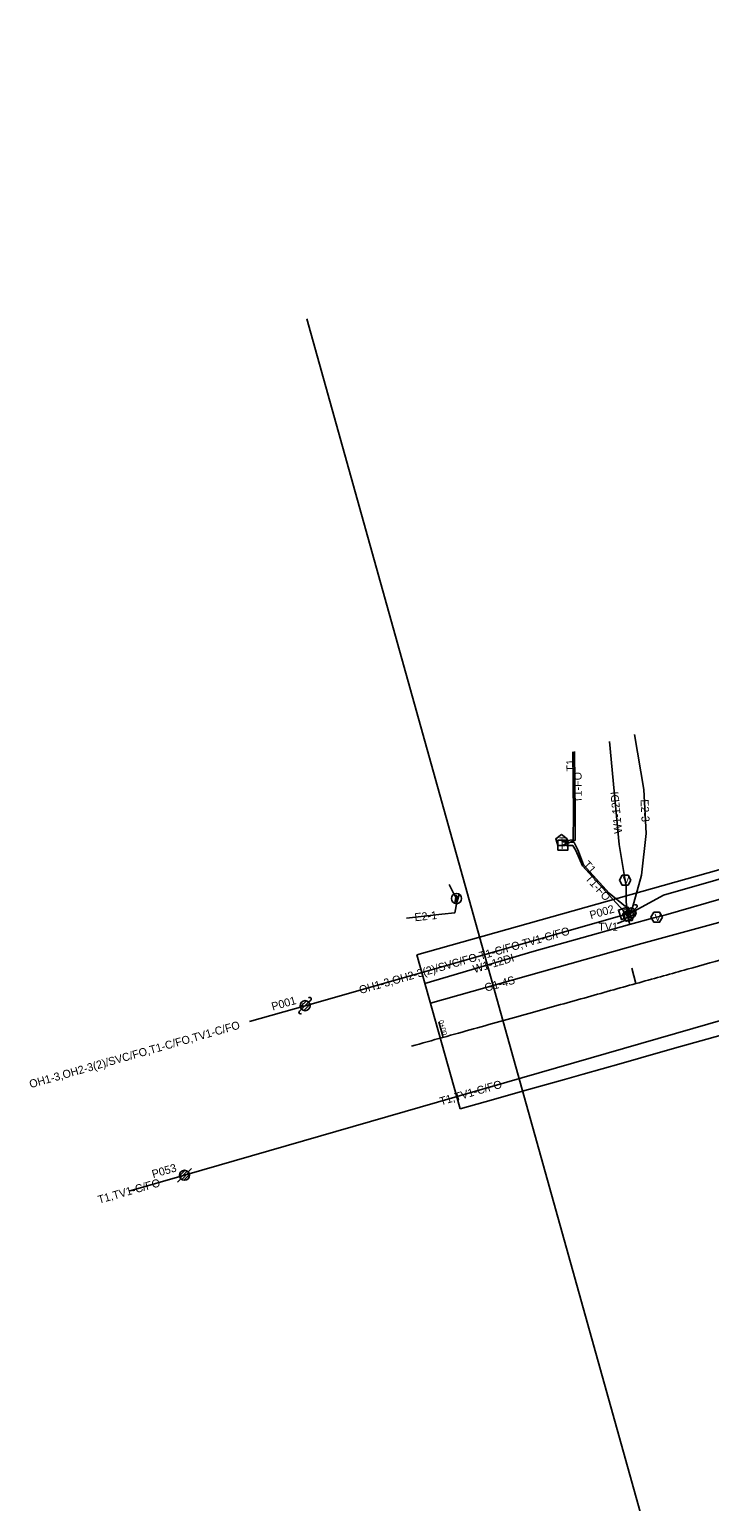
# Model space of a CAD drawing. Extents: x 1991878 to 2008544, y 770238 to 1141211.
# Drawn here: x 2002746 to 2003086, y 1138328 to 1139064 of the extents above; entities that cross this region are included whole.
import ezdxf

# ---------------------------------------------------------------- set-up
doc = ezdxf.new("R2010")
doc.units = 0
for name, color, linetype in [('Default', 7, 'Continuous'), ('RD_EX_SU_Elec', 7, 'Continuous'), ('RD_EX_SU_Gas', 7, 'Continuous'), ('RD_EX_SU_H2O', 7, 'Continuous'), ('RD_EX_SU_Ovhd', 7, 'Continuous'), ('RD_EX_SU_Pole', 7, 'Continuous'), ('RD_EX_SU_SwpLmt', 7, 'Continuous'), ('RD_EX_SU_Telecom', 7, 'Continuous'), ('RD_EX_SU_TX_Elec', 7, 'Continuous'), ('RD_EX_SU_TX_Gas', 7, 'Continuous'), ('RD_EX_SU_TX_H2O', 7, 'Continuous'), ('RD_EX_SU_TX_Ovhd', 7, 'Continuous'), ('RD_EX_SU_TX_Pole', 7, 'Continuous'), ('RD_EX_SU_TX_Telecom', 7, 'Continuous'), ('RD_HC_Cl', 7, 'Continuous')]:
    doc.layers.add(name, color=color, linetype=linetype)

msp = doc.modelspace()

# ---------------------------------------------------------------- linework, layer by layer
at = {"layer": 'RD_EX_SU_Elec'}
for points in [[(2003048.81, 1138711.86), (2003053.41, 1138684.46), (2003054.61, 1138662.45), (2003052.25, 1138641.53), (2003047.56, 1138624.68), (2003047.01, 1138622.69)], [(2002959.81, 1138629.87), (2002958.35, 1138632.58), (2002956.1, 1138636.98)], [(2002934.89, 1138620.09), (2002952.47, 1138622.12), (2002958.9, 1138622.68), (2002959.98, 1138627.91), (2002959.81, 1138629.87)]]:
    msp.add_lwpolyline(points, dxfattribs=at)
msp.add_lwpolyline([(2002961.2, 1138631.93), (2002960.19, 1138628.48), (2002959.69, 1138630.35), (2002958.93, 1138627.53), (2002959.62, 1138631.44), (2002960.18, 1138629.5)], close=True, dxfattribs=at)
msp.add_circle((2002959.81, 1138629.87), 2.55, dxfattribs=at)
at = {"layer": 'RD_EX_SU_Gas'}
msp.add_lwpolyline([(2002946.83, 1138577.61), (2003002.3, 1138593.2), (2003052.38, 1138607.39), (2003100, 1138620.35), (2003147.6, 1138633.54), (2003195.99, 1138647.01), (2003243.17, 1138660.79), (2003291.92, 1138674.29), (2003299.4, 1138676.3), (2003340.19, 1138688.36), (2003366.55, 1138697.07), (2003388.03, 1138704.39), (2003411.02, 1138710.07), (2003435.92, 1138715.41), (2003485.93, 1138729.36), (2003533.07, 1138741.35), (2003581.38, 1138754.26), (2003629.65, 1138767.33), (2003677.03, 1138780.22), (2003724.13, 1138793.01)], dxfattribs=at)
at = {"layer": 'RD_EX_SU_H2O'}
for points in [[(2002944.07, 1138587.41), (2002998.58, 1138603.55), (2003046.26, 1138616.87), (2003058.35, 1138620.2), (2003064.36, 1138621.76), (2003097.18, 1138631.32), (2003107.17, 1138634.02), (2003145.34, 1138644.17), (2003181.61, 1138654.23), (2003241.02, 1138669.65), (2003290.46, 1138683.16), (2003339.39, 1138697.4), (2003386.17, 1138711.62), (2003411.15, 1138718.97), (2003435.43, 1138724.73), (2003481.87, 1138737.9), (2003530.04, 1138750.74), (2003543.13, 1138754.14), (2003579.58, 1138763.94), (2003628.26, 1138777.98), (2003687.76, 1138792.8), (2003723.04, 1138803.19)], [(2003036.31, 1138708.34), (2003041.11, 1138656.99), (2003043.92, 1138639.93), (2003044.6, 1138636.08), (2003044.6, 1138628.03), (2003045.85, 1138618.62), (2003046.34, 1138616.89)]]:
    msp.add_lwpolyline(points, dxfattribs=at)
for points in [[(2003046.93, 1138639.05), (2003045.49, 1138641.55), (2003042.6, 1138641.55), (2003041.16, 1138639.05), (2003042.6, 1138636.55), (2003045.49, 1138636.55)], [(2003062.75, 1138620.54), (2003061.3, 1138623.04), (2003058.42, 1138623.04), (2003056.97, 1138620.54), (2003058.42, 1138618.04), (2003061.3, 1138618.04)]]:
    msp.add_lwpolyline(points, close=True, dxfattribs=at)
at = {"layer": 'RD_EX_SU_Ovhd'}
for p, q in [((2002884.17, 1138576.34), (2003047.01, 1138622.69)), ((2002823.93, 1138491.55), (2003110.94, 1138574.45)), ((2002856.35, 1138568.43), (2002884.17, 1138576.34)), ((2002796.11, 1138483.63), (2002823.93, 1138491.55))]:
    msp.add_line(p, q, dxfattribs=at)
msp.add_lwpolyline([(2003047.01, 1138622.69), (2003063.18, 1138631.62), (2003222.43, 1138677.3), (2003240.87, 1138678.3)], dxfattribs=at)
at = {"layer": 'RD_EX_SU_Pole'}
for p, q in [((2003044.6, 1138622.05), (2003047.66, 1138625.11)), ((2003045.25, 1138620.93), (2003048.78, 1138624.46)), ((2003046.37, 1138620.28), (2003049.43, 1138623.34)), ((2003048.78, 1138624.46), (2003049.84, 1138625.52)), ((2003044.19, 1138619.87), (2003045.25, 1138620.93)), ((2002881.75, 1138575.7), (2002884.81, 1138578.76)), ((2002885.93, 1138578.11), (2002886.99, 1138579.17)), ((2002881.34, 1138573.52), (2002882.4, 1138574.58)), ((2002882.4, 1138574.58), (2002885.93, 1138578.11)), ((2002883.52, 1138573.93), (2002886.58, 1138576.99)), ((2002821.45, 1138491.21), (2002824.26, 1138494.03)), ((2002821.83, 1138490.18), (2002825.29, 1138493.64)), ((2002822.53, 1138489.47), (2002826, 1138492.94)), ((2002823.55, 1138489.07), (2002826.4, 1138491.93)), ((2002825.7, 1138493.32), (2002827.35, 1138494.97)), ((2002820.51, 1138488.12), (2002822.16, 1138489.78)), ((2002825.45, 1138489.56), (2002825.91, 1138490.02))]:
    msp.add_line(p, q, dxfattribs=at)
for centre in [(2003047.01, 1138622.69), (2002884.17, 1138576.34), (2002823.93, 1138491.55)]:
    msp.add_circle(centre, 2.5, dxfattribs=at)
for centre, start, end in [((2003049.31, 1138626.05), 315.01158, 135.01158), ((2003044.72, 1138619.33), 135.01158, 315.01158), ((2002886.46, 1138579.7), 315.01158, 135.01158), ((2002881.87, 1138572.99), 135.01158, 315.01158)]:
    msp.add_arc(centre, 0.75, start, end, dxfattribs=at)
at = {"layer": 'RD_EX_SU_SwpLmt'}
for p, q in [((2002940.04, 1138601.78), (2003113.75, 1138650.78)), ((2002961.67, 1138524.77), (2002940.04, 1138601.78))]:
    msp.add_line(p, q, dxfattribs=at)
msp.add_open_spline([(2002961.67, 1138524.77), (2003135.44, 1138573.78), (2003750.13, 1138748.44), (2003835.13, 1138778.08), (2003876.89, 1138794.57), (2003884.84, 1138797.79)], degree=3, dxfattribs=at)
at = {"layer": 'RD_EX_SU_Telecom'}
for points in [[(2003012.22, 1138658.88), (2003013.76, 1138658.76), (2003018.14, 1138659.27), (2003018.3, 1138672.31), (2003017.92, 1138703.17)], [(2003012.99, 1138656.63), (2003014.22, 1138657.11), (2003019.02, 1138659), (2003019.04, 1138672.4), (2003018.84, 1138703.43)], [(2003047.01, 1138622.69), (2003046.01, 1138622.47), (2003044.21, 1138625.88), (2003036.09, 1138632.51), (2003023.24, 1138646.76), (2003020.39, 1138654.2), (2003018.59, 1138657.86), (2003013.28, 1138658.18), (2003012.22, 1138658.88)], [(2003043.87, 1138622.51), (2003043.3, 1138623.72), (2003036.03, 1138631.6), (2003022.69, 1138646.32), (2003019.43, 1138653.92), (2003017.89, 1138656.49), (2003014.39, 1138656.46), (2003012.99, 1138656.63)], [(2003047.01, 1138622.69), (2003046.56, 1138621.87), (2003046.22, 1138621.38), (2003045.73, 1138621.38), (2003045.19, 1138621.3), (2003044.65, 1138621.88), (2003043.87, 1138622.51)]]:
    msp.add_lwpolyline(points, dxfattribs=at)
for points in [[(2003012.22, 1138661.88), (2003009.37, 1138659.81), (2003010.46, 1138656.46), (2003013.98, 1138656.46), (2003015.07, 1138659.81)], [(2003015.49, 1138659.13), (2003010.5, 1138659.13), (2003010.5, 1138654.13), (2003015.49, 1138654.13)], [(2003045.45, 1138625.68), (2003040.7, 1138624.09), (2003042.29, 1138619.35), (2003047.03, 1138620.93)], [(2003045.73, 1138624.38), (2003042.88, 1138622.31), (2003043.97, 1138618.95), (2003047.49, 1138618.95), (2003048.58, 1138622.31)]]:
    msp.add_lwpolyline(points, close=True, dxfattribs=at)
at = {"layer": 'RD_EX_SU_TX_Telecom'}
msp.add_line((2003040.15, 1138617.37), (2003043.97, 1138618.95), dxfattribs=at)
at = {"layer": 'RD_HC_Cl'}
for p, q in [((2002885.03, 1138919.69), (2003081, 1138217.99)), ((2003047.33, 1138595.11), (2003049.48, 1138587.4)), ((2002951.02, 1138568.21), (2002953.17, 1138560.5))]:
    msp.add_line(p, q, dxfattribs=at)
msp.add_open_spline([(2002937.27, 1138556.06), (2003081.12, 1138596.24), (2003224.54, 1138636.27), (2003324.8, 1138664.72), (2003440.8, 1138697.76), (2003610.3, 1138743.13), (2003753.45, 1138782.34), (2003851.96, 1138815.09), (2003945.32, 1138855.48), (2004023.07, 1138899.74), (2004117.46, 1138962.96), (2004239.69, 1139051.13), (2004401.3, 1139168.16), (2004522.74, 1139256.47), (2004724.1, 1139402.13), (2005003.72, 1139590.96), (2005189.76, 1139724.82), (2005285.27, 1139787.25)], degree=2, dxfattribs=at)

# ---------------------------------------------------------------- texts
at = {"layer": 'Default'}
msp.add_text('+', height=4, rotation=360, dxfattribs=at).set_placement((2002881.47, 1138574.34))
at = {"layer": 'RD_EX_SU_H2O'}
for p in [(2003042.83, 1138637.18), (2003058.65, 1138618.66)]:
    msp.add_text('V', height=3.75, dxfattribs=at).set_placement(p)
at = {"layer": 'RD_EX_SU_Telecom'}
for s, height, p in [('T', 3.75, (2003010.99, 1138656.66)), ('C', 4, (2003044.5, 1138619.38))]:
    msp.add_text(s, height=height, dxfattribs=at).set_placement(p)
for rotation, p in [(359.99935, (2003011.86, 1138654.63)), (18.46636, (2003043.43, 1138620.26))]:
    msp.add_text('F', height=4, rotation=rotation, dxfattribs=at).set_placement(p)
at = {"layer": 'RD_EX_SU_TX_Elec'}
for s, rotation, p in [('E2-3', 273.10687, (2003051.71, 1138679.37)), ('E2-1', 5.89046, (2002939.03, 1138618.53))]:
    msp.add_text(s, height=4, rotation=rotation, dxfattribs=at).set_placement(p)
at = {"layer": 'RD_EX_SU_TX_Gas'}
msp.add_text('G1-4S', height=4, rotation=15.69989, dxfattribs=at).set_placement((2002974.47, 1138583.28))
at = {"layer": 'RD_EX_SU_TX_H2O'}
for rotation, p in [(95.33821, (2003042.62, 1138662.54)), (16.49169, (2002968.72, 1138592.6))]:
    msp.add_text('W1-12DI', height=4, rotation=rotation, dxfattribs=at).set_placement(p)
at = {"layer": 'RD_EX_SU_TX_Ovhd'}
for s, rotation, p in [('OH1-3,OH2-3(2)/SVC/FO,T1-C/FO,TV1-C/FO', 15.88706, (2002911.79, 1138582.13)), ('OH1-3,OH2-3(2)/SVC/FO,T1-C/FO,TV1-C/FO', 15.88706, (2002747.04, 1138535.08)), ('T1,TV1-C/FO', 16.11171, (2002952.04, 1138526.47)), ('T1,TV1-C/FO', 15.88706, (2002781.27, 1138477.32))]:
    msp.add_text(s, height=4, rotation=rotation, dxfattribs=at).set_placement(p)
at = {"layer": 'RD_EX_SU_TX_Pole'}
for s, rotation, p in [('P002', 15.88706, (2003026.97, 1138619.57)), ('P001', 15.88706, (2002868.04, 1138573.86)), ('P053', 16.11171, (2002808.28, 1138490.12))]:
    msp.add_text(s, height=4, rotation=rotation, dxfattribs=at).set_placement(p)
at = {"layer": 'RD_EX_SU_TX_Telecom'}
for s, rotation, p in [('T1', 90.69551, (2003018.78, 1138693.35)), ('T1-FO', 90.36439, (2003022.4, 1138677.7)), ('T1', 312.04151, (2003022.76, 1138646.6)), ('T1-FO', 312.17701, (2003023.83, 1138639.76))]:
    msp.add_text(s, height=4, rotation=rotation, dxfattribs=at).set_placement(p)
msp.add_text('TV1', height=4, dxfattribs=at).set_placement((2003030.68, 1138613.81))
at = {"layer": 'RD_HC_Cl'}
msp.add_text('0+00', height=2.5, rotation=285.60521, dxfattribs=at).set_placement((2002950.85, 1138568.79))

doc.saveas('drawing.dxf')
